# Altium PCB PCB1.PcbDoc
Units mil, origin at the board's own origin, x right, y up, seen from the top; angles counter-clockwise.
Board outline 6380 x 3360 mil, 2 copper layers (Top Layer, Bottom Layer); 138 components, 156 nets, 538 pads, 20 vias.
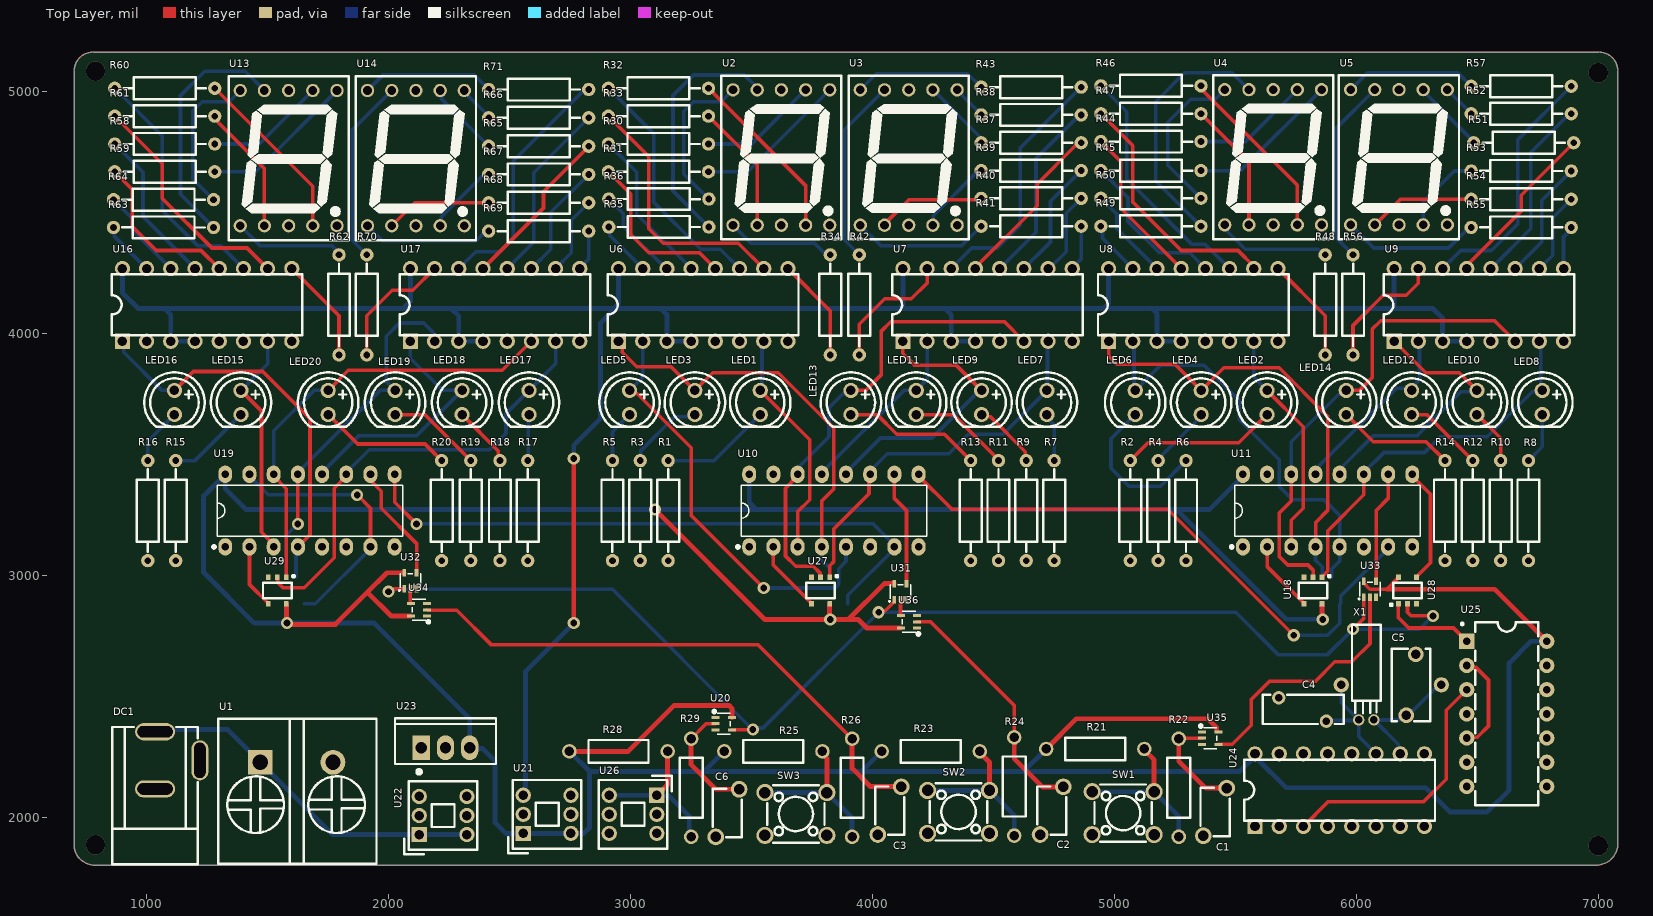
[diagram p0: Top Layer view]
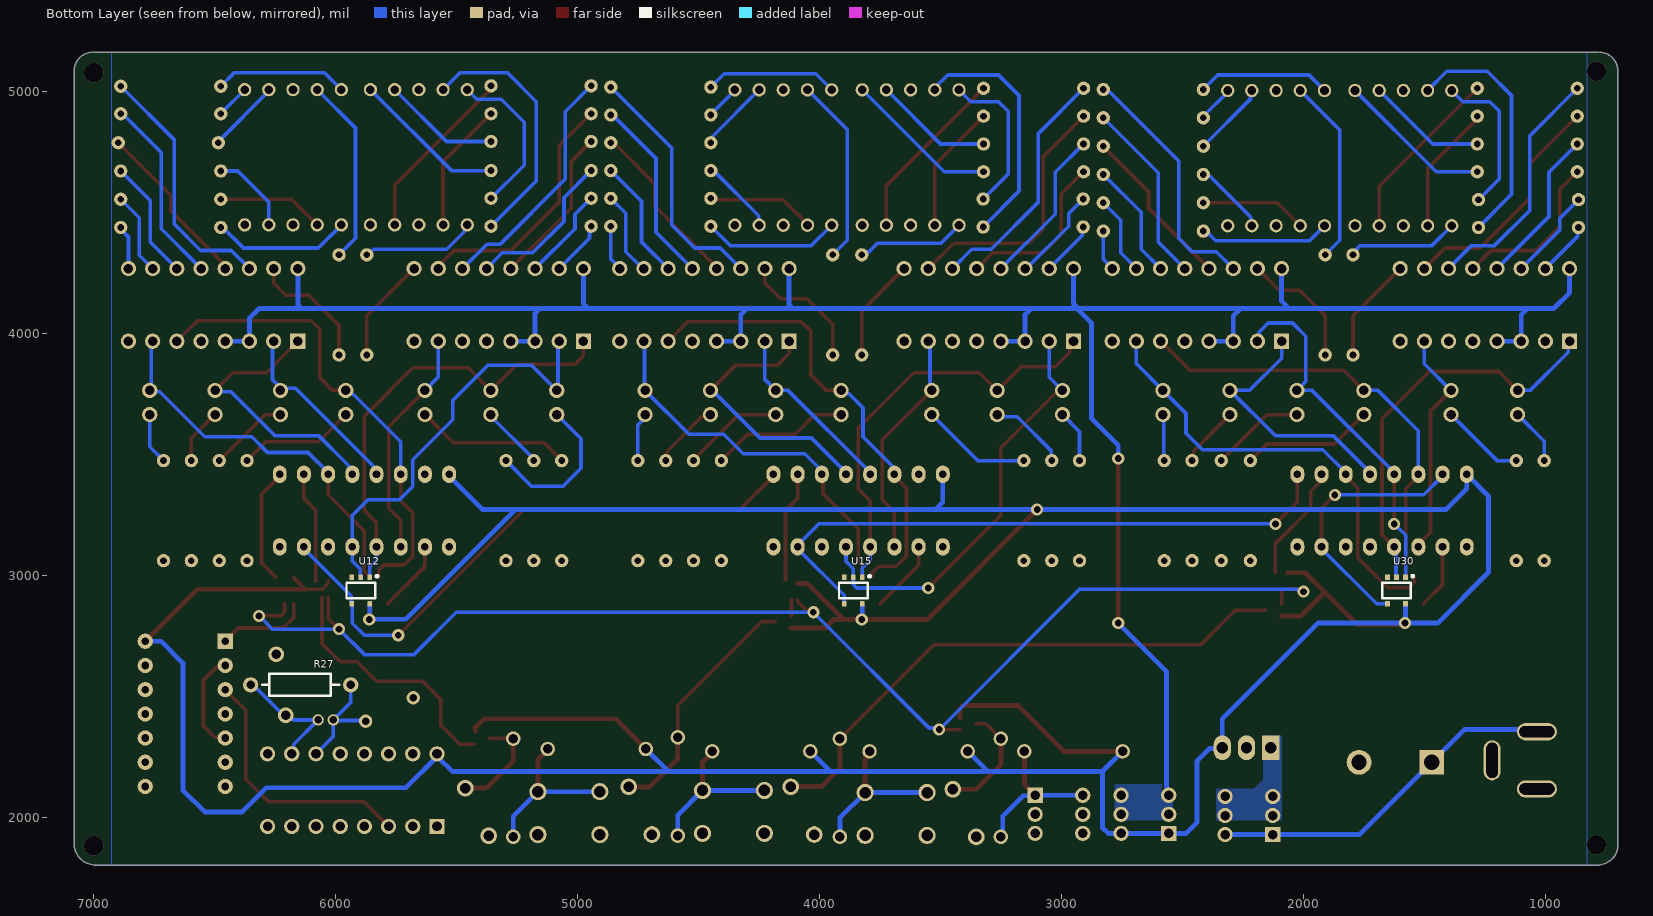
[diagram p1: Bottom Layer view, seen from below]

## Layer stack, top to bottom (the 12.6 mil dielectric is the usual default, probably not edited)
Top Solder: solder mask 0.4, Solder Resist, Dk 3.5
Top Layer: signal copper 1.4
Dielectric 1: dielectric 12.6, FR-4, Dk 4.8
Bottom Layer: signal copper 1.4
Bottom Solder: solder mask 0.4, Solder Resist, Dk 3.5

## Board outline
785,1805 6990,1805 ccw(c6990,1895) 7080,1895 7080,5085 ccw(c7000.01,5085.01) 7000,5165 780,5165 ccw(c780,5085) 700,5085 700,1890 ccw(c785,1890)

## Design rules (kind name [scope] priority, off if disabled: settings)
Clearance [All] p1: gap=10 ignorepadtopadclearanceinfootprint=FALSE except(8: SMDPad-SMDPad)
PolygonConnect PolygonConnect_5 [All vs IsNamedPolygon('NONET_L01_P005')] p1: connectstyle=Direct reliefconductorwidth=10 reliefentries=4 polygonreliefangle="90 Angle" airgapwidth=10
PolygonConnect PolygonConnect_4 [All vs IsNamedPolygon('NONET_L02_P005')] p2: connectstyle=Direct reliefconductorwidth=10 reliefentries=4 polygonreliefangle="90 Angle" airgapwidth=10
PolygonConnect PolygonConnect_3 [All vs IsNamedPolygon('NONET_L-01_P-001')] p3: connectstyle=Direct reliefconductorwidth=10 reliefentries=4 polygonreliefangle="90 Angle" airgapwidth=10
PolygonConnect PolygonConnect_2 [All vs IsNamedPolygon('NONET_L-01_P-001')] p4: thpad.connectstyle=Direct thpad.reliefconductorwidth=10 thpad.reliefentries=4 thpad.polygonreliefangle="90 Angle" thpad.airgapwidth=10 smdpad.connectstyle=Direct smdpad.reliefconductorwidth=10 smdpad.reliefentries=4 smdpad.polygonreliefangle="90 Angle" smdpad.airgapwidth=10 via.connectstyle=Relief via.reliefconductorwidth=10 via.reliefentries=4 via.polygonreliefangle="90 Angle" via.airgapwidth=10
PolygonConnect PolygonConnect_1 [All vs IsNamedPolygon('NONET_L-01_P-001')] p5: connectstyle=Direct reliefconductorwidth=10 reliefentries=4 polygonreliefangle="90 Angle" airgapwidth=10
PolygonConnect [All] p6: connectstyle=Relief reliefconductorwidth=10 reliefentries=4 polygonreliefangle="90 Angle" airgapwidth=10
RoutingVias [All] p1: holewidth=28 width=50 viastyle="Through Hole" minholewidth=28 minwidth=50 maxholewidth=28 maxwidth=50
SolderMaskExpansion [All] p1: expansion=4 istentingtop=FALSE
SupplyNets "Schematic Supply Nets_3" [InNet('GND')] p1: voltage=0.000
SupplyNets "Schematic Supply Nets_1" [InNet('+D5V')] p2: voltage=0.000
SupplyNets "Schematic Supply Nets" [InNet('+5')] p3: voltage=0.000
Width [All] p1: maxlimit=50 minlimit=10 preferedwidth=15 minimp=50.000000 maximp=50.000000 favimp=50.000000
30 further rules are at their usual default settings.

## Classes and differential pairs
component class Display_SEC_MIN: LED1 LED2 LED3 LED4 LED5 LED6 LED7 LED8 LED9 LED10 LED11 LED12 LED13 LED14 R1 R2 R3 R4 R5 R6 R7 R8 R9 R10 R11 R12 R13 R14 R30 R31 R32 R33 R34 R35 R36 R37 R38 R39 R40 R41 R42 R43 R44 R45 R46 R47 R48 R49 R50 R51 R52 R53 R54 R55 R56 R57 U2 U3 U4 U5 U6 U7 U8 U9 U10 U11
component class Display_Hour: LED15 LED16 LED17 LED18 LED19 LED20 R15 R16 R17 R18 R19 R20 R58 R59 R60 R61 R62 R63 R64 R65 R66 R67 R68 R69 R70 R71 U12 U13 U14 U15 U16 U17 U18 U19 U20 U27 U28 U29 U30 U31 U32 U33 U34 U35 U36
component class CLK_SW: C1 C2 C3 C4 C5 C6 DC1 R21 R22 R23 R24 R25 R26 R27 R28 R29 SW1 SW2 SW3 U1 U21 U22 U23 U24 U25 U26 X1

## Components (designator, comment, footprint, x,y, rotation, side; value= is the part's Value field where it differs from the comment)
C1 "100pF" CAP-TH_L5.0-W3.0-P5.00-D0.6-S2.45 5415,2025 r90 top locked
C2 "100pF" CAP-TH_L5.0-W3.0-P5.00-D0.6-S2.45 4740,2030 r90 top locked
C3 "100pF" CAP-TH_L5.0-W3.0-P5.00-D0.6-S2.45 4070,2030 r90 top locked
C4 "560pF" CAP-TH_L8.5-W3.0-P5.00-D0.6-S2.5 5776.58,2448.23 r0 top
C5 "22pF" CAP-TH_L7.4-W4.0-P6.40-D0.5-S1.00 6225,2550 r270 top
C6 "100pF" CAP-TH_L5.0-W3.0-P5.00-D0.6-S2.45 3400,2020 r90 top locked
DC1 "DC-005-2.5A-2.0" CONN-TH_DC-005-2.5A-2.0 1127.53,2238.1 r90 top locked
LED1 "WP7113ID" LED-TH_BD5.0-P2.54-FD 3535.52,3716.7 r270 top locked
LED2 "WP7113ID" LED-TH_BD5.0-P2.54-FD 5630,3716.7 r270 top locked
LED3 "WP7113ID" LED-TH_BD5.0-P2.54-FD 3265.52,3716.7 r270 top locked
LED4 "WP7113ID" LED-TH_BD5.0-P2.54-FD 5357.5,3716.7 r270 top locked
LED5 "WP7113ID" LED-TH_BD5.0-P2.54-FD 2995.52,3716.7 r270 top locked
LED6 "WP7113ID" LED-TH_BD5.0-P2.54-FD 5085,3716.7 r270 top locked
LED7 "WP7113ID" LED-TH_BD5.0-P2.54-FD 4720.21,3716.7 r270 top locked
LED8 "WP7113ID" LED-TH_BD5.0-P2.54-FD 6767.15,3716.7 r270 top locked
LED9 "WP7113ID" LED-TH_BD5.0-P2.54-FD 4450.21,3716.7 r270 top locked
LED10 "WP7113ID" LED-TH_BD5.0-P2.54-FD 6497.15,3716.7 r270 top locked
LED11 "WP7113ID" LED-TH_BD5.0-P2.54-FD 4180.21,3716.7 r270 top locked
LED12 "WP7113ID" LED-TH_BD5.0-P2.54-FD 6227.15,3716.7 r270 top locked
LED13 "WP7113ID" LED-TH_BD5.0-P2.54-FD 3910.21,3716.7 r270 top locked
LED14 "WP7113ID" LED-TH_BD5.0-P2.54-FD 5957.15,3716.7 r270 top locked
LED15 "WP7113ID" LED-TH_BD5.0-P2.54-FD 1390,3716.7 r270 top locked
LED16 "WP7113ID" LED-TH_BD5.0-P2.54-FD 1115,3716.7 r270 top locked
LED17 "WP7113ID" LED-TH_BD5.0-P2.54-FD 2580.21,3716.7 r270 top locked
LED18 "WP7113ID" LED-TH_BD5.0-P2.54-FD 2303.55,3716.7 r270 top locked
LED19 "WP7113ID" LED-TH_BD5.0-P2.54-FD 2026.88,3716.7 r270 top locked
LED20 "WP7113ID" LED-TH_BD5.0-P2.54-FD 1750.21,3716.7 r270 top locked
R1 "330Ω" RES-TH_BD2.3-L6.5-P10.50-D0.5 3155,3270 r270 top locked
R2 "330Ω" RES-TH_BD2.3-L6.5-P10.50-D0.5 5065,3270 r270 top locked
R3 "330Ω" RES-TH_BD2.3-L6.5-P10.50-D0.5 3040,3270 r270 top locked
R4 "330Ω" RES-TH_BD2.3-L6.5-P10.50-D0.5 5180,3270 r270 top locked
R5 "330Ω" RES-TH_BD2.3-L6.5-P10.50-D0.5 2925,3270 r270 top locked
R6 "330Ω" RES-TH_BD2.3-L6.5-P10.50-D0.5 5295,3270 r270 top locked
R7 "330Ω" RES-TH_BD2.3-L6.5-P10.50-D0.5 4750,3270 r90 top locked
R8 "330Ω" RES-TH_BD2.3-L6.5-P10.50-D0.5 6710,3270 r90 top locked
R9 "330Ω" RES-TH_BD2.3-L6.5-P10.50-D0.5 4635,3270 r90 top locked
R10 "330Ω" RES-TH_BD2.3-L6.5-P10.50-D0.5 6595,3270 r90 top locked
R11 "330Ω" RES-TH_BD2.3-L6.5-P10.50-D0.5 4520,3270 r90 top locked
R12 "330Ω" RES-TH_BD2.3-L6.5-P10.50-D0.5 6480,3270 r90 top locked
R13 "330Ω" RES-TH_BD2.3-L6.5-P10.50-D0.5 4405,3270 r90 top locked
R14 "330Ω" RES-TH_BD2.3-L6.5-P10.50-D0.5 6365,3270 r90 top locked
R15 "330Ω" RES-TH_BD2.3-L6.5-P10.50-D0.5 1120,3270 r270 top locked
R16 "330Ω" RES-TH_BD2.3-L6.5-P10.50-D0.5 1005,3270 r270 top locked
R17 "330Ω" RES-TH_BD2.3-L6.5-P10.50-D0.5 2575,3270 r90 top locked
R18 "330Ω" RES-TH_BD2.3-L6.5-P10.50-D0.5 2460.04,3270 r90 top locked
R19 "330Ω" RES-TH_BD2.3-L6.5-P10.50-D0.5 2339.48,3270 r90 top locked
R20 "330Ω" RES-TH_BD2.3-L6.5-P10.50-D0.5 2218.93,3270 r90 top locked
R21 "10kΩ" RES-TH_BD2.4-L6.3-P10.30-D0.6 4920,2285 r180 top locked
R22 "10kΩ" RES-TH_BD2.4-L6.3-P10.30-D0.6 5265,2125 r270 top locked
R23 "10kΩ" RES-TH_BD2.4-L6.3-P10.30-D0.6 4240,2275 r180 top locked
R24 "10kΩ" RES-TH_BD2.4-L6.3-P10.30-D0.6 4585,2130 r270 top locked
R25 "10kΩ" RES-TH_BD2.4-L6.3-P10.30-D0.6 3590,2275 r180 top locked
R26 "10kΩ" RES-TH_BD2.4-L6.3-P10.30-D0.6 3915,2125 r270 top locked
R27 "10MΩ" RES-TH_BD2.2-L6.5-P10.50-D0.6 6143.31,2550 r0 bottom
R28 "10kΩ" RES-TH_BD2.4-L6.3-P10.30-D0.6 2950,2275 r180 top locked
R29 "10kΩ" RES-TH_BD2.4-L6.3-P10.30-D0.6 3250,2125 r270 top locked
R30 "330Ω" RES-TH_BD2.3-L6.5-P10.50-D0.5 3115,4785 r0 top locked
R31 "330Ω" RES-TH_BD2.3-L6.5-P10.50-D0.5 3115,4670 r0 top locked
R32 "330Ω" RES-TH_BD2.3-L6.5-P10.50-D0.5 3115,5015 r0 top locked
R33 "330Ω" RES-TH_BD2.3-L6.5-P10.50-D0.5 3115,4900 r0 top locked
R34 "330Ω" RES-TH_BD2.3-L6.5-P10.50-D0.5 3825,4120 r90 top locked
R35 "330Ω" RES-TH_BD2.3-L6.5-P10.50-D0.5 3116.75,4441.96 r0 top locked
R36 "330Ω" RES-TH_BD2.3-L6.5-P10.50-D0.5 3116.75,4557.57 r0 top locked
R37 "330Ω" RES-TH_BD2.3-L6.5-P10.50-D0.5 4655,4790 r180 top locked
R38 "330Ω" RES-TH_BD2.3-L6.5-P10.50-D0.5 4655,4905 r180 top locked
R39 "330Ω" RES-TH_BD2.3-L6.5-P10.50-D0.5 4655,4675 r180 top locked
R40 "330Ω" RES-TH_BD2.3-L6.5-P10.50-D0.5 4655,4560 r180 top locked
R41 "330Ω" RES-TH_BD2.3-L6.5-P10.50-D0.5 4655,4445 r180 top locked
R42 "330Ω" RES-TH_BD2.3-L6.5-P10.50-D0.5 3945,4120 r90 top locked
R43 "330Ω" RES-TH_BD2.3-L6.5-P10.50-D0.5 4655,5020 r180 top locked
R44 "330Ω" RES-TH_BD2.3-L6.5-P10.50-D0.5 5150,4795 r0 top locked
R45 "330Ω" RES-TH_BD2.3-L6.5-P10.50-D0.5 5150,4675 r0 top locked
R46 "330Ω" RES-TH_BD2.3-L6.5-P10.50-D0.5 5150,5025 r0 top locked
R47 "330Ω" RES-TH_BD2.3-L6.5-P10.50-D0.5 5150,4910 r0 top locked
R48 "330Ω" RES-TH_BD2.3-L6.5-P10.50-D0.5 5870,4120 r90 top locked
R49 "330Ω" RES-TH_BD2.3-L6.5-P10.50-D0.5 5150,4445 r0 top locked
R50 "330Ω" RES-TH_BD2.3-L6.5-P10.50-D0.5 5150,4560.83 r0 top locked
R51 "330Ω" RES-TH_BD2.3-L6.5-P10.50-D0.5 6690,4790 r180 top locked
R52 "330Ω" RES-TH_BD2.3-L6.5-P10.50-D0.5 6680,4910 r180 top locked
R53 "330Ω" RES-TH_BD2.3-L6.5-P10.50-D0.5 6680,4673.33 r180 top locked
R54 "330Ω" RES-TH_BD2.3-L6.5-P10.50-D0.5 6680,4556.67 r180 top locked
R55 "330Ω" RES-TH_BD2.3-L6.5-P10.50-D0.5 6680,4440 r180 top locked
R56 "330Ω" RES-TH_BD2.3-L6.5-P10.50-D0.5 5985,4120 r90 top locked
R57 "330Ω" RES-TH_BD2.3-L6.5-P10.50-D0.5 6680,5023.33 r180 top locked
R58 "330Ω" RES-TH_BD2.3-L6.5-P10.50-D0.5 1075,4785 r0 top locked
R59 "330Ω" RES-TH_BD2.3-L6.5-P10.50-D0.5 1075,4670 r0 top locked
R60 "330Ω" RES-TH_BD2.3-L6.5-P10.50-D0.5 1075,5015 r0 top locked
R61 "330Ω" RES-TH_BD2.3-L6.5-P10.50-D0.5 1075,4900 r0 top locked
R62 "330Ω" RES-TH_BD2.3-L6.5-P10.50-D0.5 1795,4120 r90 top locked
R63 "330Ω" RES-TH_BD2.3-L6.5-P10.50-D0.5 1070,4440 r0 top locked
R64 "330Ω" RES-TH_BD2.3-L6.5-P10.50-D0.5 1070,4555 r0 top locked
R65 "330Ω" RES-TH_BD2.3-L6.5-P10.50-D0.5 2620,4776 r180 top locked
R66 "330Ω" RES-TH_BD2.3-L6.5-P10.50-D0.5 2620,4893 r180 top locked
R67 "330Ω" RES-TH_BD2.3-L6.5-P10.50-D0.5 2620,4659 r180 top locked
R68 "330Ω" RES-TH_BD2.3-L6.5-P10.50-D0.5 2620,4542 r180 top locked
R69 "330Ω" RES-TH_BD2.3-L6.5-P10.50-D0.5 2620,4425 r180 top locked
R70 "330Ω" RES-TH_BD2.3-L6.5-P10.50-D0.5 1910,4120 r90 top locked
R71 "330Ω" RES-TH_BD2.3-L6.5-P10.50-D0.5 2620,5010 r180 top locked
SW1 "TS665CJ" SW-TH_4P-L6.0-W6.0-P4.50-LS6.5 5035,2020 r0 top locked
SW2 "TS665CJ" SW-TH_4P-L6.0-W6.0-P4.50-LS6.5 4355,2025 r0 top locked
SW3 "TS665CJ" SW-TH_4P-L6.0-W6.0-P4.50-LS6.5 3682.95,2016.42 r0 top locked
U1 "DBT50G-7.62-2P" CONN-TH_2P-P7.62_L15.2-W16.7-EX4.2 1620,2230 r0 top locked
U2 "HDSP-5501" LED-SEG-TH_HDSP-A 3623.03,4729.02 r0 top locked
U3 "HDSP-5501" LED-SEG-TH_HDSP-A 4149.09,4729.02 r0 top locked
U4 "HDSP-5501" LED-SEG-TH_HDSP-A 5655,4730 r0 top locked
U5 "HDSP-5501" LED-SEG-TH_HDSP-A 6175,4730 r0 top locked
U6 "CD4511BE" DIP-16_L19.8-W6.5-P2.54-LS7.6-BL 3300,4120 r0 top locked
U7 "CD4511BE" DIP-16_L19.8-W6.5-P2.54-LS7.6-BL 4475.01,4120 r0 top locked
U8 "CD4511BE" DIP-16_L19.8-W6.5-P2.54-LS7.6-BL 5325.01,4120 r0 top locked
U9 "CD4511BE" DIP-16_L19.8-W6.5-P2.54-LS7.6-BL 6505.01,4120 r0 top locked
U10 "CD4518BE" DIP-16_L19.3-W6.4-P2.54-LS7.6-BL 3840,3270 r0 top locked
U11 "CD4518BE" DIP-16_L19.3-W6.4-P2.54-LS7.6-BL 5880,3270 r0 top locked
U12 "BD7LS08G-CTL" SSOP-5_L3.0-W1.6-P0.95-LS2.8-BR 5895,2940 r90 bottom locked
U13 "HDSP-5501" LED-SEG-TH_HDSP-A 1586.86,4726.42 r0 top locked
U14 "HDSP-5501" LED-SEG-TH_HDSP-A 2112.92,4726.42 r0 top locked
U15 "BD7LS08G-CTL" SSOP-5_L3.0-W1.6-P0.95-LS2.8-BR 3860,2940 r90 bottom
U16 "CD4511BE" DIP-16_L19.8-W6.5-P2.54-LS7.6-BL 1250.01,4120 r0 top locked
U17 "CD4511BE" DIP-16_L19.8-W6.5-P2.54-LS7.6-BL 2440,4120 r0 top locked
U18 "BD7LS08G-CTL" SSOP-5_L3.0-W1.6-P0.95-LS2.8-BR 5820,2940 r90 top locked
U19 "CD4518BE" DIP-16_L19.3-W6.4-P2.54-LS7.6-BL 1675,3270 r0 top locked
U20 "SN74AHC1GU04DCKR" SOT-353_L2.1-W1.3-P0.65-LS2.3-BR 3385,2390 r180 top
U21 "PS-7054DVB-6PL" SW-TH_6P-L7.0-W7.0-P2.00 2655,2015 r180 top locked
U22 "PS-7054DVB-6PL" SW-TH_6P-L7.0-W7.0-P2.00 2225,2010 r180 top locked
U23 "L7805CV-DG" TO-220-3_L10.0-W4.5-P2.54-L 2235,2290 r0 top locked
U24 "CD4060BE" DIP-16_L19.8-W6.5-P2.54-LS7.6-BL 5930,2115 r0 top locked
U25 "CD4013BE" DIP-14_L19.2-W6.6-P2.54-LS10.9-BL 6620.35,2430 r270 top
U26 "PS-7054DVB-6PL" SW-TH_6P-L7.0-W7.0-P2.00 3010,2015 r0 top locked
U27 "BD7LS08G-CTL" SSOP-5_L3.0-W1.6-P0.95-LS2.8-BR 3785,2940 r90 top locked
U28 "BD7LS08G-CTL" SSOP-5_L3.0-W1.6-P0.95-LS2.8-BR 6210,2940 r270 top
U29 "BD7LS08G-CTL" SSOP-5_L3.0-W1.6-P0.95-LS2.8-BR 1540,2940 r90 top locked
U30 "BD7LS08G-CTL" SSOP-5_L3.0-W1.6-P0.95-LS2.8-BR 1615,2940 r90 bottom locked
U31 "TC7SET32FU,LJ(CT" TSSOP-5_L2.0-W1.3-P0.65-LS2.1-BR 4115,2935 r270 top
U32 "TC7SET32FU,LJ(CT" TSSOP-5_L2.0-W1.3-P0.65-LS2.1-BR 2090,2980 r270 top
U33 "TC7SET32FU,LJ(CT" TSSOP-5_L2.0-W1.3-P0.65-LS2.1-BR 6055,2945 r270 top
U34 "SN74AHC1GU04DCKR" SOT-353_L2.1-W1.3-P0.65-LS2.3-BR 2125,2860 r0 top
U35 "SN74AHC1GU04DCKR" SOT-353_L2.1-W1.3-P0.65-LS2.3-BR 5395,2330 r180 top
U36 "SN74AHC1GU04DCKR" SOT-353_L2.1-W1.3-P0.65-LS2.3-BR 4150,2810 r0 top
X1 "32.768kHz" OSC-TH_BD3.1-P0.8-D0.3 6040,2405 r270 top

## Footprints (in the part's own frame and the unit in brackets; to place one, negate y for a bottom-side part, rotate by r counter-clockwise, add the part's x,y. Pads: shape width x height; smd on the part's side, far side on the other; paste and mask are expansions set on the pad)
CAP-TH_L5.0-W3.0-P5.00-D0.6-S2.45 [mm]
  round 1.75 hole 1.1 paste-2539.97 mask+0.05: 1(-2.5,1.225) 2(2.5,-1.225)
  silkscreen extent -2.54,-1.52 2.54,1.52
CAP-TH_L7.4-W4.0-P6.40-D0.5-S1.00 [mm]
  round 1.65 hole 1 copper offset 0,0 paste-2539.97 mask+0.05: 1(-3.2,0.5) 2(3.2,-0.5)
  silkscreen extent -3.81,-2.03 3.81,2.03
CAP-TH_L8.5-W3.0-P5.00-D0.6-S2.5 [mm]
  round 1.4 hole 0.8: 1(-2.5,1.225) 2(2.5,-1.225)
  silkscreen extent -4.19,-1.52 4.32,1.52
CONN-TH_2P-P7.62_L15.2-W16.7-EX4.2 [mm]
  rect 2.6x2.6 hole 1.6 paste-2539.97 mask+0.051: 1(-3.81,0)
  round 2.6 hole 1.6 paste-2539.97 mask+0.051: 2(3.81,0)
  silkscreen extent -8.22,-10.65 8.38,4.55
CONN-TH_DC-005-2.5A-2.0 [mm]
  oval 1.8x4.2 hole 1.2 slot 3.7 at 90 deg paste-2539.97 mask+0.051: 1(3,2.35) 2(-3,2.35)
  oval 4.2x1.8 hole 1.2 slot 3.7 at 0 deg paste-2539.97 mask+0.051: 3(0,-2.35)
  silkscreen extent -10.9,-2.15 3.5,6.85
DIP-14_L19.2-W6.6-P2.54-LS10.9-BL [mil]
  rect 63x63 hole 32: 1(-300,-165.35)
  round 63 hole 32: 2(-200,-165.35) 3(-100,-165.35) 4(0,-165.35) 5(100,-165.35) 6(200,-165.35) 7(300,-165.35) 8(300,165.35) 9(200,165.35) 10(100,165.35) 11(0,165.35) 12(-100,165.35) 13(-200,165.35) 14(-300,165.35)
  silkscreen extent -378,-189 378,130
DIP-16_L19.3-W6.4-P2.54-LS7.6-BL [mm]
  oval 1.46x1.825 hole 0.8: 1(-8.89,-3.81) 2(-6.35,-3.81) 3(-3.81,-3.81) 4(-1.27,-3.81) 5(1.27,-3.81) 6(3.81,-3.81) 7(6.35,-3.81) 8(8.89,-3.81) 9(8.89,3.81) 10(6.35,3.81) 11(3.81,3.81) 12(1.27,3.81) 13(-1.27,3.81) 14(-3.81,3.81) 15(-6.35,3.81) 16(-8.89,3.81)
  silkscreen extent -10.22,-3.96 9.73,2.67
DIP-16_L19.8-W6.5-P2.54-LS7.6-BL [mm]
  rect 1.6x1.6 hole 1: 1(-8.89,-3.81)
  round 1.6 hole 1 copper offset 0,0: 2(-6.35,-3.81) 3(-3.81,-3.81) 4(-1.27,-3.81) 5(1.27,-3.81) 6(3.81,-3.81) 7(6.35,-3.81) 8(8.89,-3.81) 9(8.89,3.81) 10(6.35,3.81) 11(3.81,3.81) 12(1.27,3.81) 13(-1.27,3.81) 14(-3.81,3.81) 15(-6.35,3.81) 16(-8.89,3.81)
  silkscreen extent -10,-3.2 10,3.2
LED-SEG-TH_HDSP-A [mil]
  round 55.12 hole 35.43: 1(-200,-279.5) 2(-100,-279.5) 3(0,-279.5) 4(100,-279.5) 5(200,-279.5) 6(200,279.5) 7(100,279.5) 8(0,279.5) 9(-100,279.5) 10(-200,279.5)
  silkscreen extent -248,-339 248,339
LED-TH_BD5.0-P2.54-FD [mm]
  round 1.6 hole 1: 1(-1.27,0) 2(1.27,0)
  silkscreen extent -3.17,-3.17 2.54,3.17
OSC-TH_BD3.1-P0.8-D0.3 [mm]
  round 1.2 hole 0.8: 1(0,0.8) 2(0,-0.8)
  silkscreen extent -10,-1.5 -0.7,1.5
RES-TH_BD2.2-L6.5-P10.50-D0.6 [mm]
  round 1.6 hole 0.914: 1(-5.25,0) 2(5.25,0)
  silkscreen extent -4.06,-1.14 4.06,1.14
RES-TH_BD2.3-L6.5-P10.50-D0.5 [mm]
  round 1.4 hole 0.7: 1(-5.25,0) 2(5.25,0)
  silkscreen extent -4.32,-1.15 4.32,1.15
RES-TH_BD2.4-L6.3-P10.30-D0.6 [mil]
  round 60 hole 39.37: 1(-202.76,0) 2(202.76,0)
  silkscreen extent -124,-47 124,47
SOT-353_L2.1-W1.3-P0.65-LS2.3-BR [mm]
  rect 0.839x0.315 smd: 1(0.844,-0.65) 2(0.844,0) 3(0.844,0.65) 4(-0.844,0.65) 5(-0.844,-0.65)
  silkscreen extent -0.7,-1.41 1.15,1.1
SSOP-5_L3.0-W1.6-P0.95-LS2.8-BR [mm]
  rect 0.6x0.5 smd: 1(1.4,-0.95) 2(1.4,0) 3(1.4,0.95) 4(-1.4,0.95) 5(-1.4,-0.95)
  silkscreen extent -0.8,-1.83 1.63,1.5
SW-TH_4P-L6.0-W6.0-P4.50-LS6.5 [mm]
  round 1.8 hole 1.2: 1(-3.25,2.25) 2(3.25,2.25) 3(-3.25,-2.25) 4(3.25,-2.25)
  silkscreen extent -3,-3 3,3
SW-TH_6P-L7.0-W7.0-P2.00 [mm]
  rect 1.6x1.6 hole 1: 1(2.5,2)
  round 1.6 hole 1: 2(2.5,0) 3(2.5,-2) 4(-2.5,2) 5(-2.5,0) 6(-2.5,-2)
  silkscreen extent -3.6,-3.6 4.06,4.06
TO-220-3_L10.0-W4.5-P2.54-L [mm]
  rect 1.8x2.6 hole 1.2: 1(-2.54,0.005)
  oval 1.8x2.6 hole 1.2: 2(0,0.005)
  oval 1.8x2.6 hole 1.2 copper offset 0,0: 3(2.54,-0.005)
  silkscreen extent -5.3,-2.73 5.3,3.09
TSSOP-5_L2.0-W1.3-P0.65-LS2.1-BR [mm]
  rect 0.798x0.4 smd: 1(0.849,-0.65) 2(0.849,0) 3(0.849,0.65) 4(-0.849,0.65) 5(-0.849,-0.65)
  silkscreen extent -0.73,-1.22 1.09,1.08

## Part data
C1 C2 C3 C6: library part Cap_100pF_50V_ceramic, JLCPCB Part Class="Extended Part", LCSC Part Name="100pF ±10% 50V", Manufacturer=SHM(南方宏明), Manufacturer Part=DCT101K20Y5PF6FJ5A0, Temperature Coefficient=Y5P, Tolerance=±10%, Voltage Rating=50V
C4: library part Cap_560pF_50V_ceraic, JLCPCB Part Class="Extended Part", LCSC Part Name="560pF ±5% 50V", Manufacturer=SHM(南方宏明), Manufacturer Part="DCC561J34SL F6FJ5A0", Temperature Coefficient=SL, Tolerance=±5%, Voltage Rating=50V
C5: library part Cap_22pF_50V_ceramic, JLCPCB Part Class="Extended Part", LCSC Part Name="22pF ±10% 50V", Manufacturer=Dersonic(德尔创), Manufacturer Part=CC1H220KA1EDCH4B1100, Temperature Coefficient=NP0, Tolerance=±10%, Voltage Rating=50V
DC1: JLCPCB Part Class="Extended Part", Manufacturer="XKB Connection(中国星坤)"
LED1 LED2 LED3 LED4 LED5 LED6 LED7 LED8 LED9 LED10 LED11 LED12 LED13 LED14 LED15 LED16 LED17 LED18 LED19 LED20: library part D_LED_2mm_red, Emitted Color=Red, Forward Current=20mA, Forward Voltage (VF)=2V, JLCPCB Part Class="Extended Part", Lens Color="Red Lens", Manufacturer=Kingbright
R1 R2 R3 R4 R5 R6 R7 R8 R9 R10 R11 R12 R13 R14 R15 R16 R17 R18 R19 R20 R30 R31 R32 R33 R34 R35 R36 R37 R38 R39 R40 R41 R42 R43 R44 R45 R46 R47 R48 R49 R50 R51 R52 R53 R54 R55 R56 R57 R58 R59 R60 R61 R62 R63 R64 R65 R66 R67 R68 R69 R70 R71: library part Reg_330R_0.25W, JLCPCB Part Class="Extended Part", LCSC Part Name="330Ω ±1% 250mW 金属膜电阻", Manufacturer=CCO(千志电子), Manufacturer Part="MF1/4W-330Ω±1% T", Operating Temperature=-55℃~+155℃, Power(Watts)=250mW, Temperature Coefficient=±100ppm/℃, Tolerance=±1%, Voltage-Supply(Max)=250V
R21 R22 R23 R24 R25 R26 R28 R29: library part Reg_10k_0.25W, JLCPCB Part Class="Extended Part", LCSC Part Name="10kΩ ±1% 250mW 金属膜电阻", Manufacturer=Tyohm(幸亚电阻), Manufacturer Part=RN1/4W10KFT/BA1, Operating Temperature Range=-55℃~+125℃, Overload Voltage (Max)=250V, Power(Watts)=250mW, Temperature Coefficient=±50ppm/℃, Tolerance=±1%
R27: library part Reg_10M_0.25W, JLCPCB Part Class="Extended Part", LCSC Part Name="10MΩ ±5% 250mW 碳膜电阻", Manufacturer=CCO(千志电子), Manufacturer Part="CF1/4W-10MΩ±5% T", Operating Temperature=-55℃~+155℃, Power(Watts)=250mW, Temperature Coefficient=-1500ppm/℃~0ppm/℃, Tolerance=±5%, Voltage-Supply(Max)=250V
SW1 SW2 SW3: Contact Current=50mA, JLCPCB Part Class="Extended Part", LCSC Part Name="6*6*5mm 直插 轻触开关", Manufacturer="SHOU HAN(首韩)", Voltage Rating (DC)=12V
U1: JLCPCB Part Class="Extended Part", Manufacturer=DORABO(地博电气), Manufacturer Part=DBT50G-7.62-2P-BK-P
U2 U3 U4 U5 U13 U14: JLCPCB Part Class="Extended Part", Manufacturer=Broadcom/AVAGO(安华高)
U6 U7 U8 U9 U16 U17: library part CD4511BE_C507153, JLCPCB Part Class="Extended Part", LCSC Part Name="CMOS BCD 到 7 段 LED 锁存解码器驱动器", Manufacturer=HGSEMI(华冠)
U10 U11 U19: JLCPCB Part Class="Extended Part", Manufacturer=TI(德州仪器), Operating Temperature=-55℃~+125℃, Voltage - Supply=3V~18V
U12 U15 U18 U27 U28 U29 U30: library part AND_BD7LS08G-CTL, JLCPCB Part Class="Extended Part", Manufacturer=ROHM(罗姆), Operating Temperature=-40℃~+125℃, Quiescent Current (Max)=10uA, Sink Current=32mA, Supply Voltage=1.65V~5.5V
U20 U34 U35 U36: library part NOT_SN74AHC1GU04DCKR_C7472, JLCPCB Part Class="Extended Part", LCSC Part Name=单路反相器, Manufacturer=TI(德州仪器), Operating Temperature=-40℃~+85℃, Sink Current=8mA, Supply Current (Max)=1uA, Supply Voltage(Single)=2V~5.5V
U21 U22 U26: JLCPCB Part Class="Extended Part", LCSC Part Name=7*7自锁按键开关, Manufacturer=G-Switch(品赞), Operating Force=250gf
U23: Dropout Voltage=2V@(1A), JLCPCB Part Class="Extended Part", LCSC Part Name=正稳压器IC, Manufacturer=ST(意法半导体), Maximum Input Voltage=35V, Operating Temperature=0℃~+125℃, Output Current=1.5A, Output Voltage=5V, Power Supply Rejection Ratio (PSRR)=62dB@(120Hz), standby current=8mA
U24: JLCPCB Part Class="Extended Part", LCSC Part Name="CMOS 14 级纹波进位二进制计数器/除法器和振荡器", Manufacturer=HGSEMI(华冠)
U25: Clock Frequency=24MHz, Current - Output High(IOH)=6.8mA, Input Capacitance=5pF, JLCPCB Part Class="Extended Part", Manufacturer=TI(德州仪器), Operating Temperature=-55℃~+125℃, Quiescent Current=4uA, Voltage - Supply=3V~18V
U31 U32 U33: library part OR_GATE_TC7SET32FU,LJ(CT, JLCPCB Part Class="Extended Part", Manufacturer=TOSHIBA(东芝), Operating Temperature=-40℃~+85℃, Quiescent Current (Max)=2uA, Sink Current=8mA, Supply Voltage=4.5V~5.5V
X1: library part AB38T-32.768KHZ, Equivalent Series Resistance (ESR)=30kΩ, Frequency Stability(Full temperature range)=-, JLCPCB Part Class="Extended Part", LCSC Part Name="32.768kHz ±20ppm 12.5pF", Manufacturer=ABRACON, Normal temperature Frequency Tolerance=±20ppm

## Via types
v1: diameter 50, hole 28, Top Layer to Bottom Layer, 16 vias
v2: diameter 80, hole 80, Top Layer to Bottom Layer, 4 vias

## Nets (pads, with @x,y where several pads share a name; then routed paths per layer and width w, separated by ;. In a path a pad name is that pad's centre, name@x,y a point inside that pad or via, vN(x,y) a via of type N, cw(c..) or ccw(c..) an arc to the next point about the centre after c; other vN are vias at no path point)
1H1: LED17.1 U17.7 U19.11 U29.2 | length 1881.5
  Top Layer w15: U29.2 1542.34,2992.77 1542.34,2972.66 1563.79,2951.21 1651.21,2951.21 1775,3075 1775,3362.82 1825,3412.82 U19.11
  Bottom Layer w15: U19.11 1825,3427.18 1919.56,3521.75 2416.75,3521.75 2485,3590 2485,3671.49 LED17.1 2690,3876.49 U17.7
1H2: LED18.1 U17.1 U19.12 | length 1065.1
  Bottom Layer w15: U19.12 1725,3427.18 1877.82,3580 2116.84,3580 LED18.1 2223.3,3766.7 2090,3900 U17.1
1H3: LED19.1 U17.2 U19.13 U30.1 | length 1504.2
  Top Layer w15: v1(1625,3215) U19.13
  Bottom Layer w15: U30.1 1577.6,3167.6 v1(1625,3215) ; U19.13 1625,3427.18 1964.52,3766.7 LED19.1 1990,3803.58 1990,3990 2045,4045 2145,4045 2181.82,4008.18 2181.82,3978.17 U17.2
1H4: LED20.1 U17.6 U19.14 U29.1 | length 1844.9
  Top Layer w15: U19.14 1525,3412.82 1577.4,3360.41 U29.1 ; LED20.1 1833.51,3850 2470,3850 U17.6
  Bottom Layer w15: U19.14 1525,3600 1691.7,3766.7 LED20.1
1H_CLK: U10.7 U15.4 U19.9 | length 2575.7
  Top Layer w15: U19.9 2025,3305 v1(2115,3215)
  Bottom Layer w15: v1(2115,3215) 4002.18,3215 4090,3127.18 U10.7 4090,3112.82 3897.4,2920.22 U15.4
1H_EN: U19.10 U32.4 | length 485.5
  Top Layer w15: U19.10 1933.13,3411.87 1933.13,3386.87 1970,3350 1970,3280 2115.59,3134.41 U32.4
1M1: LED7.1 U7.7 U10.11 U27.1 | length 1582.2
  Top Layer w15: U27.1 3822.4,3042.4 3840,3060 3840,3195 3985,3340 3985,3415 U10.11
  Bottom Layer w15: U10.11 3990,3435 4060,3505 4315,3505 4395,3585 4538.5,3585 LED7.1 4722.61,3769.11 4722.61,3967.62 U7.7
1M2: LED9.1 U7.1 U10.12 | length 1146.7
  Top Layer w15: U7.1 4125.01,3919.99 4175,3870 4346.91,3870 LED9.1
  Bottom Layer w15: U10.12 3890,3427.18 4032.82,3570 4245,3570 4441.7,3766.7 LED9.1
1M3: LED11.1 U7.2 U10.13 | length 759.9
  Bottom Layer w15: U10.13 3790,3427.18 4129.52,3766.7 LED11.1 4225.01,3811.51 U7.2
1M4: LED13.1 U7.6 U10.14 U27.2 | length 1967.4
  Top Layer w15: U10.14 3690,3412.82 3640,3362.82 3640,3082.55 3682.55,3040 3754.79,3040 3782.66,3012.13 3782.66,2997.46 U27.2 ; LED13.1 3971.7,3766.7 4035,3830 4035,4010 4075,4050 4545.01,4050 U7.6
  Bottom Layer w15: U10.14 3698.13,3428.13 3698.13,3453.13 3820,3575 3820,3695 3877.77,3752.77 3883.29,3752.77 3897.22,3766.7 LED13.1
1M_CLK: U10.9 U11.7 U12.4 | length 2438.2
  Top Layer w15: U10.9 4190,3412.82 4327.81,3275 5220,3275 v1(5740,2755)
  Bottom Layer w15: v1(5740,2755) 5880,2755 5930.06,2805.06 5930.06,2882.54 5934.74,2887.23 5934.74,2917.56 6130,3112.82 U11.7
1M_EN: U10.10 U31.4 | length 455.4
  Top Layer w15: U10.10 4090,3320 4140,3270 4140,2985.31
1S1: LED8.1 U9.7 U11.11 U18.1 | length 1589.7
  Top Layer w15: U18.1 5857.4,2997.08 5880.96,3020.64 5880.96,3185.96 6030,3335 U11.11
  Bottom Layer w15: U11.11 6030,3427.18 6112.81,3510 6280,3510 6345,3575 6540,3575 6726.25,3761.25 6761.69,3761.25 LED8.1 6761.08,3772.77 6761.08,3963.93 U9.7
1S2: LED10.1 U9.1 U11.12 | length 1148.8
  Top Layer w15: U9.1 6285.01,3840 6423.85,3840 LED10.1
  Bottom Layer w15: U11.12 5930,3438.68 5944.82,3453.5 5944.82,3454.82 6070,3580 6250,3580 6431.25,3761.25 6491.69,3761.25 LED10.1
1S3: LED12.1 U9.2 U11.13 | length 778.3
  Bottom Layer w15: U11.13 5830,3438.68 5844.82,3453.5 5844.82,3454.82 6165,3775 6218.85,3775 LED12.1 6227.15,3777.37 6260,3810.22 6260,3965.01 U9.2
1S4: LED14.1 U9.6 U11.14 U18.2 | length 1972.4
  Top Layer w15: U11.14 5730,3310 5680,3260 5680,3080 5715,3045 5799.23,3045 5820,3024.23 U18.2 ; LED14.1 6011.7,3766.7 6065,3820 6065,4020 6100,4055 6570.01,4055 U9.6
  Bottom Layer w15: U11.14 5730,3555 5926.25,3751.25 5928.71,3751.25 5944.16,3766.7 LED14.1
1S_CLK: U11.9 U28.4 | length 479.8
  Top Layer w15: U11.9 6230,3412.82 6305,3337.82 6305,3054.68 6247.4,2997.08 U28.4
1S_EN: U11.10 U33.4 | length 462
  Top Layer w15: U33.4 6080.59,3270.59 6130,3320 U11.10
10H1: LED15.1 U16.7 U19.3 | length 951.5
  Top Layer w15: LED15.1 1475,3681.7 1475,3180 1525,3130 U19.3
  Bottom Layer w15: LED15.1 1500.01,3876.72 U16.7
10H2: LED16.1 U16.1 U19.4 U30.2 | length 1675.6
  Top Layer w15: LED16.1 1193.3,3845 1480,3845 1675,3650 1675,3170 U19.4
  Bottom Layer w15: U16.1 905.21,3964.8 905.21,3924.79 1063.3,3766.7 LED16.1 ; U30.2 1617.34,2997.46 1617.34,3112.34 U19.4
10H_EN: U19.2 U29.4 | length 267.3
  Top Layer w15: U19.2 1425,2964.45 1502.6,2886.85 U29.4
10M1: LED1.1 U6.7 U10.3 | length 961.4
  Top Layer w15: LED1.1 3740,3562.22 3740,3315 3690,3265 U10.3
  Bottom Layer w15: LED1.1 3542.76,3773.95 3542.76,3962.78 U6.7
10M2: LED3.1 U6.1 U10.4 U15.1 | length 1766.5
  Top Layer w15: U6.1 2965.21,3954.79 2965.21,3924.79 3025,3865 3167.22,3865 LED3.1 3338.81,3840 3610,3840 3740,3710 3840,3610 3840,3360 3790,3310 U10.4
  Bottom Layer w15: U10.4 3790,3065 3822.6,3032.4 U15.1
10M3: LED5.1 U6.2 U10.5 U15.2 | length 1766.3
  Top Layer w15: LED5.1 3008.5,3766.7 3022.79,3752.41 3027.59,3752.41 3250,3530 3250,3250 v1(3550,2950)
  Bottom Layer w15: LED5.1 3050,3821.19 U6.2 ; v1(3550,2950) 3845,2950 3860,2965 3860,3030.14 3890,3060.14 U10.5
10M_EN: U10.2 U27.4 | length 300.4
  Top Layer w15: U10.2 3590,3044.45 3747.6,2886.85 U27.4
10S1: LED2.1 U8.7 U11.3 | length 955.6
  Top Layer w15: LED2.1 5780,3616.7 5780,3280 5730,3230 U11.3
  Bottom Layer w15: U8.7 5575.01,3821.69 LED2.1
10S2: LED4.1 U8.1 U11.4 U12.1 | length 1842.9
  Top Layer w15: U8.1 4975.01,3909.99 5010,3875 5249.2,3875 LED4.1 5450.8,3860 5680,3860 5880,3660 5880,3270 5831.25,3221.25 5831.25,3121.25 U11.4
  Bottom Layer w15: U11.4 5830,3065 5857.6,3037.4 U12.1
10S3: LED6.1 U8.2 U11.5 U12.2 | length 1732.7
  Bottom Layer w15: U8.2 5080.01,3965 5080.01,3771.7 LED6.1 5188.3,3870 5370,3870 5515,3725 5515,3645 5680,3480 5680,3370 5735,3315 5865,3315 5930,3250 U11.5 5930,3061.57 5897.34,3028.92 5897.34,2997.46 U12.2
10S_EN: U11.2 U18.4 | length 298.3
  Top Layer w15: U11.2 5630,3039.45 5782.6,2886.85 U18.4
+5: R21.2 R23.2 R25.2 R28.2 U10.16 U11.16 U12.5 U15.5 U18.5 U19.16 U20.5 U21.1 U21.4 U23.3 U24.16 U25.14 U27.5 U28.5 U29.5 U30.5 U31.5 U32.5 U33.5 U34.5 U35.5 U36.5 | length 18639.8
  Top Layer w15: U33.5 6029.41,2970.6 6054.78,2945.22 6124.68,2945.22 6172.6,2993.15 U28.5
  Top Layer w20: U29.5 1577.56,2884.73 1577.56,2807.44 v1(1580,2805) 1585,2800 1780,2800 1912.5,2932.5 ; U32.5 1993.43,3013.43 1912.5,2932.5 ; U34.5 2010.59,2834.41 1912.5,2932.5 ; R28.2 2989.82,2275 3179.82,2465 3406.52,2465 3418.24,2453.28 U20.5 ; v1(3100,3275) 3555,2820 v1(3825,2820) ; U27.5 3822.4,2822.6 v1(3825,2820) ; U31.5 4048.43,2968.43 3900,2820 ; U36.5 4116.17,2785 3975,2785 3940,2820 3900,2820 ; R21.2 4842.24,2410 5385,2410 5421.73,2373.27 U35.5@5421.73,2359.39 ; U11.16@5530,3405 U11.16 ; U18.5 5857.56,2884.73 5857.56,2822.44 v1(5860,2820) ; 6124.68,2945.22 6570.48,2945.22 U25.14 ; v1(3825,2820) 3900,2820
  Bottom Layer w20: U30.5 1577.76,2884.73 1577.76,2807.24 v1(1580,2805) ; R28.2 2830,2192.24 ; R25.2 3304.48,2192.24 ; U10.16 3490,3305 3520,3275 ; U15.5 3822.76,2884.73 3822.76,2822.24 v1(3825,2820) ; R23.2 3954.48,2192.24 ; R21.2 4624.48,2192.24 ; U11.16 5530,3412.82 5392.19,3275 5255,3275 ; U24.16 5579.99,2247.23 5572.23,2247.23 5517.24,2192.24 4624.48,2192.24 ; U24.16@5586.14,2247.23 5708.37,2125 6285,2125 6385,2025 6540,2025 6630,2115 6630,2640 6720,2730 U25.14 ; v1@5857.6,2821.12 5708.88,2821.12 5255,3275 ; U12.5 5857.76,2884.73 5857.76,2822.24 v1(5860,2820) ; v1(1580,2805) 1940,2805 2335,2410 U23.3 2338.52,2286.28 2388.72,2286.28 2440,2235 2440,1980 2483.74,1936.26 U21.1 U21.4 2806.26,1936.26 2830,1960 2830,2192.24 ; v1(1580,2805) 1445,2805 1235,3015 1235,3170 1235,3330 U19.16 1325,3360 1410,3275 v1(3100,3275) 3520,3275 ; 2830,2192.24 3304.48,2192.24 ; 3304.48,2192.24 3954.48,2192.24 ; 3520,3275 5255,3275 ; 3954.48,2192.24 4624.48,2192.24
+D5V: U6.3 U6.4 U6.16 U7.3 U7.4 U7.16 U8.3 U8.4 U8.16 U9.3 U9.4 U9.16 U16.3 U16.4 U16.16 U17.3 U17.4 U17.16 U21.2 U21.3 U21.5 U21.6 | length 10052
  Top Layer w20: v1(2765,2805) v1(2765,3485)
  Bottom Layer w20: U16.16 900.01,4169.99 965,4105 1075,4105 ; U16.4 U16.3 1100.01,4079.99 1075,4105 ; U17.16 2090,4135 2060,4105 ; U17.4 U17.3 2290,4075 2260,4105 ; U21.3 2564.8,2101.97 2564.8,2126.75 2565,2126.95 2565,2605 v1(2765,2805) ; v1(2765,3485) 2765,3540 2875,3650 2875,4045 2930,4100 2930,4105 ; U6.16 2950,4125 2930,4105 ; U6.4 U6.3 3150,4080 3125,4105 ; U7.16 4125.01,4120.01 4110,4105 ; U7.4 U7.3 4325.01,4079.99 4300,4105 ; U8.16 4975.01,4125.01 4955,4105 ; U8.4 U8.3 5175.01,4084.99 5155,4105 ; 6140.54,4105.04 6155.01,4119.52 U9.16 ; U9.4 U9.3 6355,4064.22 6314.22,4105 5155,4105 ; 1075,4105 2060,4105 ; 2060,4105 2260,4105 ; 2260,4105 2930,4105 ; 2930,4105 3125,4105 ; 3125,4105 4110,4105 ; 4110,4105 4300,4105 ; 4300,4105 4955,4105 ; 4955,4105 5155,4105
GND: C1.1 C2.1 C3.1 C4.1 C5.1 C6.1 DC1.2 DC1.3 R1.2 R2.2 R3.2 R4.2 R5.2 R6.2 R7.1 R8.1 R9.1 R10.1 R11.1 R12.1 R13.1 R14.1 R15.2 R16.2 R17.1 R18.1 R19.1 R20.1 SW1.3 SW1.4 SW2.3 SW2.4 SW3.3 SW3.4 U1.2 U2.3 U2.5 U2.8 U3.3 U3.5 U3.8 U4.3 U4.5 U4.8 U5.3 U5.5 U5.8 U6.5 U6.8 U7.5 U7.8 U8.5 U8.8 U9.5 U9.8 U10.1 U10.8 U10.15 U11.1 U11.8 U11.15 U12.3 U13.3 U13.5 U13.8 U14.3 U14.5 U14.8 U15.3 U16.5 U16.8 U17.5 U17.8 U18.3 U19.1 U19.8 U20.3 U23.2 U24.8 U25.4 U25.6 U25.7 U26.2 U26.3 U26.5 U26.6 U27.3 U28.3 U29.3 U30.3 U31.3 U32.3 U33.3 U34.3 U35.3 U36.3
H_RES: U19.7 U19.15 U30.4 | length 1096.4
  Top Layer w15: v1(1870,3335) 1925,3280 U19.7
  Bottom Layer w15: U19.15 1425,3412.82 1502.82,3335 v1(1870,3335) ; U30.4 1697.07,2884.89 1925,3112.82 U19.7
NetC1_2: C1.2 R22.1 U35.2 | length 434.9
  Top Layer w15: R22.1 5266.12,2328.88 5360.64,2328.88 U35.2
  Top Layer w20: R22.1 5265,2235 5376.58,2123.42 C1.2
NetC2_2: C2.2 R24.1 U36.2 | length 1016.2
  Top Layer w15: U36.2 4240,2810 4585,2465 R24.1
  Top Layer w20: R24.1 4585,2245 4701.57,2128.43 C2.2
NetC3_2: C3.2 R26.1 U34.2 | length 2334.9
  Top Layer w15: U34.2 2159.54,2858.7 2281.3,2858.7 2425,2715 3527.76,2715 R26.1
  Top Layer w20: R26.1 3915,2205 3990,2130 4116.65,2130 C3.2
NetC4_2: C4.2 R27.1 U24.11 X1.2 | length 476.4
  Bottom Layer w15: C4.2 5877.5,2402.5 X1.2@6006,2402.5 ; R27.1 5936.61,2476.88 X1.2 6008.5,2336.5 U24.11
NetC5_2: C5.2 R27.2 U24.10 X1.1 | length 523.5
  Bottom Layer w15: U24.10 6171.77,2273.22 6171.77,2304.72 X1.1 6174.13,2405 6193.15,2424.02 C5.2 6214.67,2424.02 6340.65,2550 R27.2
NetC6_2: C6.2 R29.1 U20.2 | length 475.6
  Top Layer w15: R29.1 3312.24,2390 U20.2
  Top Layer w20: R29.1 3250,2220 3351.58,2118.42 C6.2
NetDC1_1: DC1.1 U1.1 U22.1 U22.4 | length 1471.7
  Bottom Layer w20: DC1.1 1043.8,2365 1335,2365 U1.1 1768.74,1931.26 U22.1 U22.4
NetLED1_2: LED1.2 R1.1 | length 459.2
  Bottom Layer w15: R1.1 3345.5,3476.69 LED1.2
NetLED2_2: LED2.2 R2.1 | length 643.7
  Top Layer w15: R2.1 5138.31,3550 5513.3,3550 LED2.2
NetLED3_2: LED3.2 R3.1 | length 326.7
  Bottom Layer w15: R3.1 3041.24,3477.94 3041.24,3516.24 3182.52,3657.52 3256.33,3657.52 LED3.2
NetLED4_2: LED4.2 R4.1 | length 263.5
  Bottom Layer w15: R4.1 5180,3482.95 5357.5,3660.45 LED4.2
NetLED5_2: LED5.2 R5.1 | length 219.2
  Bottom Layer w15: R5.1 2925,3596.19 LED5.2
NetLED6_2: LED6.2 R6.1 | length 648.4
  Bottom Layer w15: LED6.2 4985,3566.7 4985,3445 5060,3370 5188.31,3370 R6.1
NetLED7_2: LED7.2 R7.2 | length 202.4
  Bottom Layer w15: LED7.2 4720.21,3653.72 4750,3623.92 R7.2
NetLED8_2: LED8.2 R8.2 | length 213.7
  Bottom Layer w15: R8.2 6767.15,3533.84 LED8.2
NetLED9_2: LED9.2 R9.2 | length 283
  Top Layer w15: LED9.2 4459.34,3657.57 4487.43,3657.57 4631.26,3513.74 4631.26,3480.44 R9.2
NetLED10_2: LED10.2 R10.2 | length 230.5
  Top Layer w15: LED10.2 6595,3568.85 R10.2
NetLED11_2: LED11.2 R11.2 | length 420.4
  Top Layer w15: LED11.2 4333.3,3666.7 4339.99,3660.01 4520,3480 R11.2
NetLED12_2: LED12.2 R12.2 | length 331.6
  Top Layer w15: LED12.2 6289.99,3666.7 R12.2
NetLED13_2: LED13.2 R13.2 | length 573.5
  Top Layer w15: LED13.2 4018.3,3666.7 4100,3585 4296.69,3585 R13.2
NetLED14_2: LED14.2 R14.2 | length 486.6
  Top Layer w15: LED14.2 6068.85,3555 6286.69,3555 R14.2
NetLED15_2: LED15.2 R15.1 | length 348.7
  Bottom Layer w15: R15.1 1199.99,3476.69 LED15.2
NetLED16_2: LED16.2 R16.1 | length 235.6
  Bottom Layer w15: R16.1 1005,3556.7 LED16.2
NetLED17_2: LED17.2 R17.2 | length 192.2
  Bottom Layer w15: R17.2 2577.61,3479.3 2577.61,3664.1 LED17.2
NetLED18_2: LED18.2 R18.2 | length 254.8
  Top Layer w15: LED18.2 2452.36,3517.89 2452.36,3484.37 R18.2
NetLED19_2: LED19.2 R19.2 | length 391.3
  Top Layer w15: LED19.2 2149.47,3666.7 R19.2
NetLED20_2: LED20.2 R20.2 | length 547.4
  Top Layer w15: LED20.2 1871.92,3545 2150.62,3545 R20.2
NetR21_1: R21.1 R22.2 SW1.1 SW1.2 | length 677.6
  Top Layer w20: R21.1 5122.76,2280.53 5162.95,2240.34 SW1.2
  Bottom Layer w20: SW1.1 SW1.2 5265,2006.53 R22.2
NetR23_1: R23.1 R24.2 SW2.1 SW2.2 | length 662.6
  Top Layer w20: R23.1 4442.76,2270.53 4482.95,2230.34 SW2.2
  Bottom Layer w20: SW2.1 SW2.2 4585,2011.53 R24.2
NetR25_1: R25.1 R26.2 SW3.1 SW3.2 | length 659.3
  Top Layer w20: R25.1 3792.76,2264.18 3810.91,2246.03 SW3.2
  Bottom Layer w20: SW3.1 SW3.2 3915,2000.9 R26.2
NetR28_1: R28.1 R29.2 U26.1 U26.4 | length 654.6
  Top Layer w20: U26.1 3152.76,2138.09 R28.1
  Bottom Layer w20: U26.4 U26.1 3110.35,2091.8 3158.2,2091.8 3242.35,2007.65 3242.35,1929.9 R29.2
NetR30_1: R30.1 U6.13 | length 656.5
  Bottom Layer w15: R30.1 3025,4668.31 3025,4495 U6.13
NetR30_2: R30.2 U2.7 | length 493.9
  Bottom Layer w15: R30.2 3499.51,4785 U2.7
NetR31_1: R31.1 U6.12 | length 706
  Top Layer w15: R31.1 3000,4578.31 3000,4410 3075,4335 3285,4335 U6.12
NetR31_2: R31.2 U2.6 | length 641.6
  Bottom Layer w15: R31.2 3484.51,4670 U2.6
NetR32_1: R32.1 U6.11 | length 1016.2
  Bottom Layer w15: R32.1 3095,4828.31 3095,4545 3290,4350 3370,4350 U6.11
NetR32_2: R32.2 U2.4 | length 731.7
  Top Layer w15: R32.2 3723.03,4613.66 U2.4
NetR33_1: R33.1 U6.10 | length 1077.4
  Top Layer w15: R33.1 3075,4733.31 3075,4435 3135,4375 3445,4375 U6.10
NetR33_2: R33.2 U2.2 | length 533.9
  Top Layer w15: R33.2 3523.03,4698.66 U2.2
NetR34_1: R34.1 U6.9 | length 429.2
  Top Layer w15: U6.9 3825,4095 R34.1
NetR34_2: R34.2 U2.1 | length 452.8
  Bottom Layer w15: U2.1 3497.55,4375 3760,4375 3796.26,4338.74 3802.09,4338.74 3814.14,4326.69 R34.2
NetR35_1: R35.1 U6.15 | length 229.9
  Bottom Layer w15: R35.1 2914.45,4437.58 2914.45,4405.55 U6.15
NetR35_2: R35.2 U2.9 | length 1018.2
  Bottom Layer w15: R35.2 3175,4590.4 3175,4985 3260,5070 3470,5070 3523.03,5016.97 U2.9
NetR36_1: R36.1 U6.14 | length 389.9
  Bottom Layer w15: R36.1 2970,4497.63 2970,4445 3144.99,4270.01 U6.14
NetR36_2: R36.2 U2.10 | length 645
  Bottom Layer w15: R36.2 3220,4661.01 3220,4920 3260,4960 3374.51,4960 U2.10
NetR37_1: R37.1 U7.13 | length 707.7
  Top Layer w15: U7.13 4425,4275 4680,4530 4680,4620 4835.45,4775.45 4836.28,4775.45 4850.83,4790 R37.1
NetR37_2: R37.2 U3.7 | length 301
  Bottom Layer w15: U3.7 4440.63,4816.98 4440.63,4797.67 R37.2
NetR38_1: R38.1 U7.12 | length 778.4
  Bottom Layer w15: U7.12 4675,4419.99 4675,4725 4855,4905 R38.1
NetR38_2: R38.2 U3.6 | length 144.6
  Bottom Layer w15: U3.6 4349.09,5006.37 4448.31,4907.15 R38.2
NetR39_1: R39.1 U7.11 | length 503
  Bottom Layer w15: U7.11 4735,4379.99 4735,4548.31 R39.1
NetR39_2: R39.2 U3.4 | length 314.9
  Bottom Layer w15: U3.4 4250.49,4450.92 4250.49,4488.92 4428.89,4667.32 4440.63,4667.32 R39.2
NetR40_1: R40.1 U7.10 | length 349.5
  Bottom Layer w15: U7.10 4730.01,4270.01 4800,4340 4800,4498.31 R40.1
NetR40_2: R40.2 U3.2 | length 447.7
  Top Layer w15: U3.2 4049.09,4454.09 4150,4555 4443.31,4555 R40.2
NetR41_1: R41.1 U7.9 | length 190.2
  Bottom Layer w15: U7.9 4825,4273 4861.69,4309.69 R41.1
NetR41_2: R41.2 U3.1 | length 567.4
  Bottom Layer w15: U3.1 4033.61,4365 4368.31,4365 R41.2
NetR42_1: R42.1 U7.15 | length 537.1
  Top Layer w15: R42.1 3945,4040 4050,4145 4160,4145 4225,4210 U7.15
NetR42_2: R42.2 U3.9 | length 774.7
  Bottom Layer w15: R42.2 3885,4386.69 3885,4844.43 U3.9
NetR43_1: R43.1 U7.14 | length 1033.8
  Bottom Layer w15: U7.14 4410.01,4355 4515,4355 4610,4450 4610,4768.31 R43.1
NetR43_2: R43.2 U3.10 | length 549.5
  Bottom Layer w15: U3.10 4015.57,5075 4393.31,5075 R43.2
NetR44_1: R44.1 U8.13 | length 662.4
  Top Layer w15: R44.1 5025.49,4712.81 5025.49,4519.52 U8.13
NetR44_2: R44.2 U4.7 | length 487.2
  Bottom Layer w15: R44.2 5540.5,4795 U4.7
NetR45_1: R45.1 U8.12 | length 657
  Bottom Layer w15: R45.1 5055,4563.31 5055,4465 5185,4335 5310.01,4335 U8.12
NetR45_2: R45.2 U4.6 | length 636.9
  Bottom Layer w15: R45.2 5520.5,4675 U4.6
NetR46_1: R46.1 U8.11 | length 1007.5
  Bottom Layer w15: R46.1 5050,4918.31 5050,4640 5320,4370 5375.01,4370 U8.11
NetR46_2: R46.2 U4.4 | length 739.5
  Top Layer w15: R46.2 5356.69,5014.14 5371.24,4999.59 5371.24,4998.76 5755,4615 U4.4
NetR47_1: R47.1 U8.10 | length 1039.3
  Top Layer w15: R47.1 5075,4778.31 5075,4545 5275,4345 5510,4345 5575,4280 U8.10
NetR47_2: R47.2 U4.2 | length 541.6
  Top Layer w15: R47.2 5555,4711.69 U4.2
NetR48_1: R48.1 U8.9 | length 437.5
  Top Layer w15: U8.9 5870,4075.01 R48.1
NetR48_2: R48.2 U4.1 | length 475.4
  Bottom Layer w15: U4.1 5455,4439.64 5467.65,4427 5467.65,4422.35 5540,4350 5841.15,4350 5864.46,4326.69 R48.2
NetR49_1: R49.1 U8.15 | length 229.5
  Bottom Layer w15: R49.1 4950.06,4438.25 4950.06,4394.94 5015,4330 U8.15
NetR49_2: R49.2 U4.9 | length 1056.2
  Bottom Layer w15: R49.2 5170,4631.69 5170,4960 5290,5080 5484.5,5080 U4.9
NetR50_1: R50.1 U8.14 | length 386.8
  Bottom Layer w15: R50.1 5010,4494.14 5010,4435.01 U8.14
NetR50_2: R50.2 U4.10 | length 661.5
  Bottom Layer w15: R50.2 5220,4697.52 5220,4875 5315,4970 5415.5,4970 U4.10
NetR51_1: R51.1 U9.13 | length 702.9
  Top Layer w15: U9.13 6455,4282.97 6680,4507.97 6680,4573.31 R51.1
NetR51_2: R51.2 U5.7 | length 305.8
  Bottom Layer w15: U5.7 6275,5003.9 6483.31,4795.6 R51.2
NetR52_1: R52.1 U9.12 | length 781.3
  Bottom Layer w15: U9.12 6720,4434.99 6720,4750 6880,4910 R52.1
NetR52_2: R52.2 U5.6 | length 140.2
  Bottom Layer w15: U5.6 6375,5008.9 6473.31,4910.6 R52.2
NetR53_1: R53.1 U9.11 | length 499.3
  Bottom Layer w15: U9.11 6765,4380.01 6765,4551.64 R53.1
NetR53_2: R53.2 U5.4 | length 346
  Bottom Layer w15: U5.4 6275,4545 6403.33,4673.33 R53.2
NetR54_1: R54.1 U9.10 | length 341.2
  Bottom Layer w15: U9.10 6810,4325.01 6810,4479.98 R54.1
NetR54_2: R54.2 U5.2 | length 442.3
  Top Layer w15: U5.2 6181.17,4556.67 R54.2
NetR55_1: R55.1 U9.9 | length 183.1
  Bottom Layer w15: U9.9 6855.01,4400.88 6886.69,4432.56 R55.1
NetR55_2: R55.2 U5.1 | length 573.1
  Bottom Layer w15: U5.1 6070.5,4355 6380,4355 6465,4440 R55.2
NetR56_1: R56.1 U9.15 | length 524.2
  Top Layer w15: R56.1 5985,4035 6110,4160 6205,4160 6255.01,4210.01 U9.15
NetR56_2: R56.2 U5.9 | length 776.7
  Bottom Layer w15: R56.2 5916.69,4395 5916.69,4851.19 U5.9
NetR57_1: R57.1 U9.14 | length 1048.5
  Bottom Layer w15: U9.14 6429.99,4345 6555,4345 6555.86,4344.14 6665,4453.28 6665,4801.64 R57.1
NetR57_2: R57.2 U5.10 | length 551
  Bottom Layer w15: U5.10 6045.5,5080 6416.64,5080 R57.2
NetR58_1: R58.1 U16.13 | length 652.4
  Bottom Layer w15: R58.1 985,4668.31 985,4485.01 U16.13
NetR58_2: R58.2 U13.7 | length 496.7
  Bottom Layer w15: R58.2 1465.94,4785 U13.7
NetR59_1: R59.1 U16.12 | length 687.2
  Top Layer w15: R59.1 940,4598.31 940,4445 1040,4345 1225.01,4345 U16.12
NetR59_2: R59.2 U13.6 | length 644.3
  Bottom Layer w15: R59.2 1450.94,4670 U13.6
NetR60_1: R60.1 U16.11 | length 1020.9
  Bottom Layer w15: R60.1 1065,4818.31 1065,4510 1210,4365 1305.01,4365 U16.11
NetR60_2: R60.2 U13.4 | length 735.9
  Top Layer w15: R60.2 1686.86,4609.83 U13.4
NetR61_1: R61.1 U16.10 | length 976.6
  Top Layer w15: R61.1 1065,4703.31 1065,4560 1270,4355 1415.01,4355 U16.10
NetR61_2: R61.2 U13.2 | length 538.1
  Top Layer w15: R61.2 1281.69,4889.14 1296.24,4874.59 1296.24,4873.76 1486.86,4683.14 U13.2
NetR62_1: R62.1 U16.9 | length 437.5
  Top Layer w15: U16.9 1795,4075.01 R62.1
NetR62_2: R62.2 U13.1 | length 462.8
  Bottom Layer w15: U13.1 1468.78,4365 1764.94,4365 1795,4334.94 R62.2
NetR63_1: R63.1 U16.15 | length 226.6
  Bottom Layer w15: R63.1 867.06,4436.25 867.06,4402.95 U16.15
NetR63_2: R63.2 U13.9 | length 1022.7
  Bottom Layer w15: R63.2 1140,4576.69 1140,4985 1240,5085 1407.78,5085 U13.9
NetR64_1: R64.1 U16.14 | length 383
  Bottom Layer w15: R64.1 940,4478.31 940,4430.01 U16.14
NetR64_2: R64.2 U13.10 | length 633.4
  Bottom Layer w15: R64.2 1190,4641.69 1190,4920 1230,4960 1340.94,4960 U13.10
NetR65_1: R65.1 U17.13 | length 686.9
  Top Layer w15: U17.13 2640,4520.02 2640,4587.97 2826.69,4774.66 R65.1
NetR65_2: R65.2 U14.7 | length 312.9
  Bottom Layer w15: U14.7 2218.55,5000.29 2218.55,4970.75 R65.2
NetR66_1: R66.1 U17.12 | length 762.5
  Bottom Layer w15: U17.12 2600,4380 2600,4666.31 R66.1
NetR66_2: R66.2 U14.6 | length 154.5
  Bottom Layer w15: U14.6 2312.92,4999.65 2413.31,4899.27 R66.2
NetR67_1: R67.1 U17.11 | length 487.1
  Bottom Layer w15: U17.11 2670,4350 2670,4502.31 R67.1
NetR67_2: R67.2 U14.4 | length 306.4
  Bottom Layer w15: U14.4 2217.82,4451.82 2217.82,4482.82 2386.32,4651.32 2405.63,4651.32 R67.2
NetR68_1: R68.1 U17.10 | length 328.6
  Bottom Layer w15: U17.10 2755,4335 2755,4470.31 R68.1
NetR68_2: R68.2 U14.2 | length 439.8
  Top Layer w15: U14.2 2108,4542 R68.2
NetR69_1: R69.1 U17.9 | length 170.2
  Bottom Layer w15: U17.9 2789.99,4272.97 2826.69,4309.67 R69.1
NetR69_2: R69.2 U14.1 | length 542.6
  Bottom Layer w15: U14.1 1974.84,4385 2362.45,4385 2402.45,4425 R69.2
NetR70_1: R70.1 U17.15 | length 522.5
  Top Layer w15: R70.1 1910,4075 2015,4180 2099.98,4180 U17.15
NetR70_2: R70.2 U14.9 | length 771.6
  Bottom Layer w15: R70.2 1850,4386.69 1850,4843 U14.9
NetR71_1: R71.1 U17.14 | length 1030.7
  Bottom Layer w15: U17.14 2360,4340 2460,4340 2515,4395 2515,4715 2797.95,4997.95 2803.78,4997.95 2815.83,5010 R71.1
NetR71_2: R71.2 U14.10 | length 551.8
  Bottom Layer w15: U14.10 1977,5070 2353.31,5070 R71.2
NetU20_4: U20.4 U28.2 U31.1 U32.1 U33.1 | length 5441.7
  Top Layer w15: v1(2000,2935) 2009.47,2935 2021.04,2946.57 U32.1 ; U20.4 3418.53,2364.7 3504.7,2364.7 v1(3505,2365) ; v1(4025,2850) 4031.7,2856.7 4052.37,2856.7 4089.41,2893.74 U31.1 ; v1(5985,2780) 6029.41,2824.41 U33.1 ; U28.2 6210,2850 6225,2835 v1(6315,2835)
  Bottom Layer w15: v1(2000,2935) 2006.7,2941.7 2022.98,2941.7 2026.29,2945 2925,2945 v1(3505,2365) 3511.7,2371.7 3546.7,2371.7 v1(4025,2850) 5500,2850 5675,2675 5880,2675 v1(5985,2780) 6260,2780 v1(6315,2835)
NetU22_2: U22.2 U22.3 U22.5 U22.6 U23.1
NetU24_3: U24.3 U25.3 | length 1076
  Top Layer w15: U24.3 5881.61,2066.61 6276.61,2066.61 6370,2160 6370,2445 U25.3
NetU25_1: U25.1 U28.1 | length 380.2
  Top Layer w15: U28.1 6172.6,2827.4 6215,2785 6400,2785 6431,2754 U25.1
NetU25_2: U25.2 U25.5 | length 415.6
  Top Layer w15: U25.5 6458.49,2333.49 6498.49,2333.49 6545,2380 6545,2570 6493.23,2621.77 6463.23,2621.77 U25.2
NetU31_2: U31.2 U36.4 | length 67
  Top Layer w15: U31.2 4115,2836.89 4116.3,2835.59 U36.4
NetU32_2: U32.2 U34.4 | length 62
  Top Layer w15: U32.2 2090,2886.89 2091.3,2885.59 U34.4
NetU33_2: U33.2 U35.4 | length 1052.9
  Top Layer w15: U35.4 5485.93,2304.41 5564.83,2383.31 5564.83,2489.83 5640,2565 5830,2565 5910,2645 5980,2645 6055,2720 U33.2
pads on no net: U6.6 U8.6 U10.6 U11.6 U16.2 U16.6 U19.5 U19.6 U20.1 U24.1 U24.2 U24.4 U24.5 U24.6 U24.7 U24.9 U24.12 U24.13 U24.14 U24.15 U25.8 U25.9 U25.10 U25.11 U25.12 U25.13 U34.1 U35.1 U36.1
copper on no net:
  other v2: 6998.74,1885 788.74,1889.97 6998.74,5079.97 788.74,5084.93

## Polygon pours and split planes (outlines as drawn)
GND on Bottom Layer "NONET_L02_P004" (solid, shelved, pour order 4): 785,1805 6990,1805 ccw(c6990,1895) 7080,1895 7080,5085 ccw(c7000.01,5085.01) 7000,5165 780,5165 ccw(c780,5085) 700,5085 700,1890 ccw(c785,1890)
+D5V on Bottom Layer "NONET_L-01_P-001" (solid, pour order 3): 2540,2140 2540,2135 2540,1990 2755,1990 2780,2015 2780,2140
NetU22_2 on Bottom Layer "NONET_L-01_P-001" (solid, pour order 2): 2090,2340 2090,1990 2360,1990 2360,2120 2205,2120 2165,2160 2165,2340
10H2 on Bottom Layer "10H2_L02_P001" (solid, shelved, pour order 1): 830,1805 6925,1805 6925,5165 830,5165
GND on Top Layer "NONET_L01_P005" (solid, remove dead copper, shelved, pour order 5): 785,1805 6990,1805 ccw(c6990,1895) 7080,1895 7080,5085 ccw(c7000.01,5085.01) 7000,5165 780,5165 ccw(c780,5085) 700,5085 700,1890 ccw(c785,1890)

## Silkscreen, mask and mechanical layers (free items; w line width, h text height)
Mechanical 15:
  lines w10: 835,4390 6920,4390 6920,5075 835,5075 835,4390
